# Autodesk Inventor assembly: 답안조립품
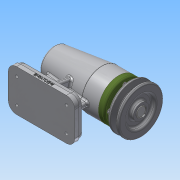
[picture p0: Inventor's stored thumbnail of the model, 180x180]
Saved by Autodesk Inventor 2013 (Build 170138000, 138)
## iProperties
Created: 2017-01
Part Number: 답안조립품
Document SubType Name: Assembly
Designer: Administrator
Author: Administrator
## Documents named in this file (11)
- C:\Users\Administrator\Desktop\470108V1010\답안조립품.iam
- C:\Users\Administrator\Desktop\470108V1010\본체.ipt
- C:\Users\Administrator\Desktop\470108V1010\축.ipt
- C:\Users\Administrator\Desktop\470108V1010\어댑터슬리브.ipt
- C:\Users\Administrator\Desktop\470108V1010\베어링 6004.ipt
- C:\Users\Administrator\Desktop\470108V1010\볼트 M4 x 12.ipt
- C:\Users\Administrator\Desktop\470108V1010\베어링 51202.ipt
- C:\Users\Administrator\Desktop\470108V1010\커버.ipt
- C:\Users\Administrator\Desktop\470108V1010\키 5 x 5 x 16.ipt
- C:\Users\Administrator\Desktop\470108V1010\V벨트풀리.ipt
- C:\Users\Administrator\Desktop\470108V1010\멈춤나사 M3x8.ipt
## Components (6 placed, 2 different names)
1. ISO 4762 M4 x 12:1
2. V벨트풀리:1 — 각도:2
3. ISO 4762 M4 x 12:2
4. ISO 4762 M4 x 12:3
5. ISO 4762 M4 x 12:4
6. ISO 4762 M4 x 12:5
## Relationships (1: Angle 1)
- 각도:2 [Angle]: V벨트풀리:1
